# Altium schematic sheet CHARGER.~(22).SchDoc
size A3; SheetNumber: 2; SheetTotal: 14
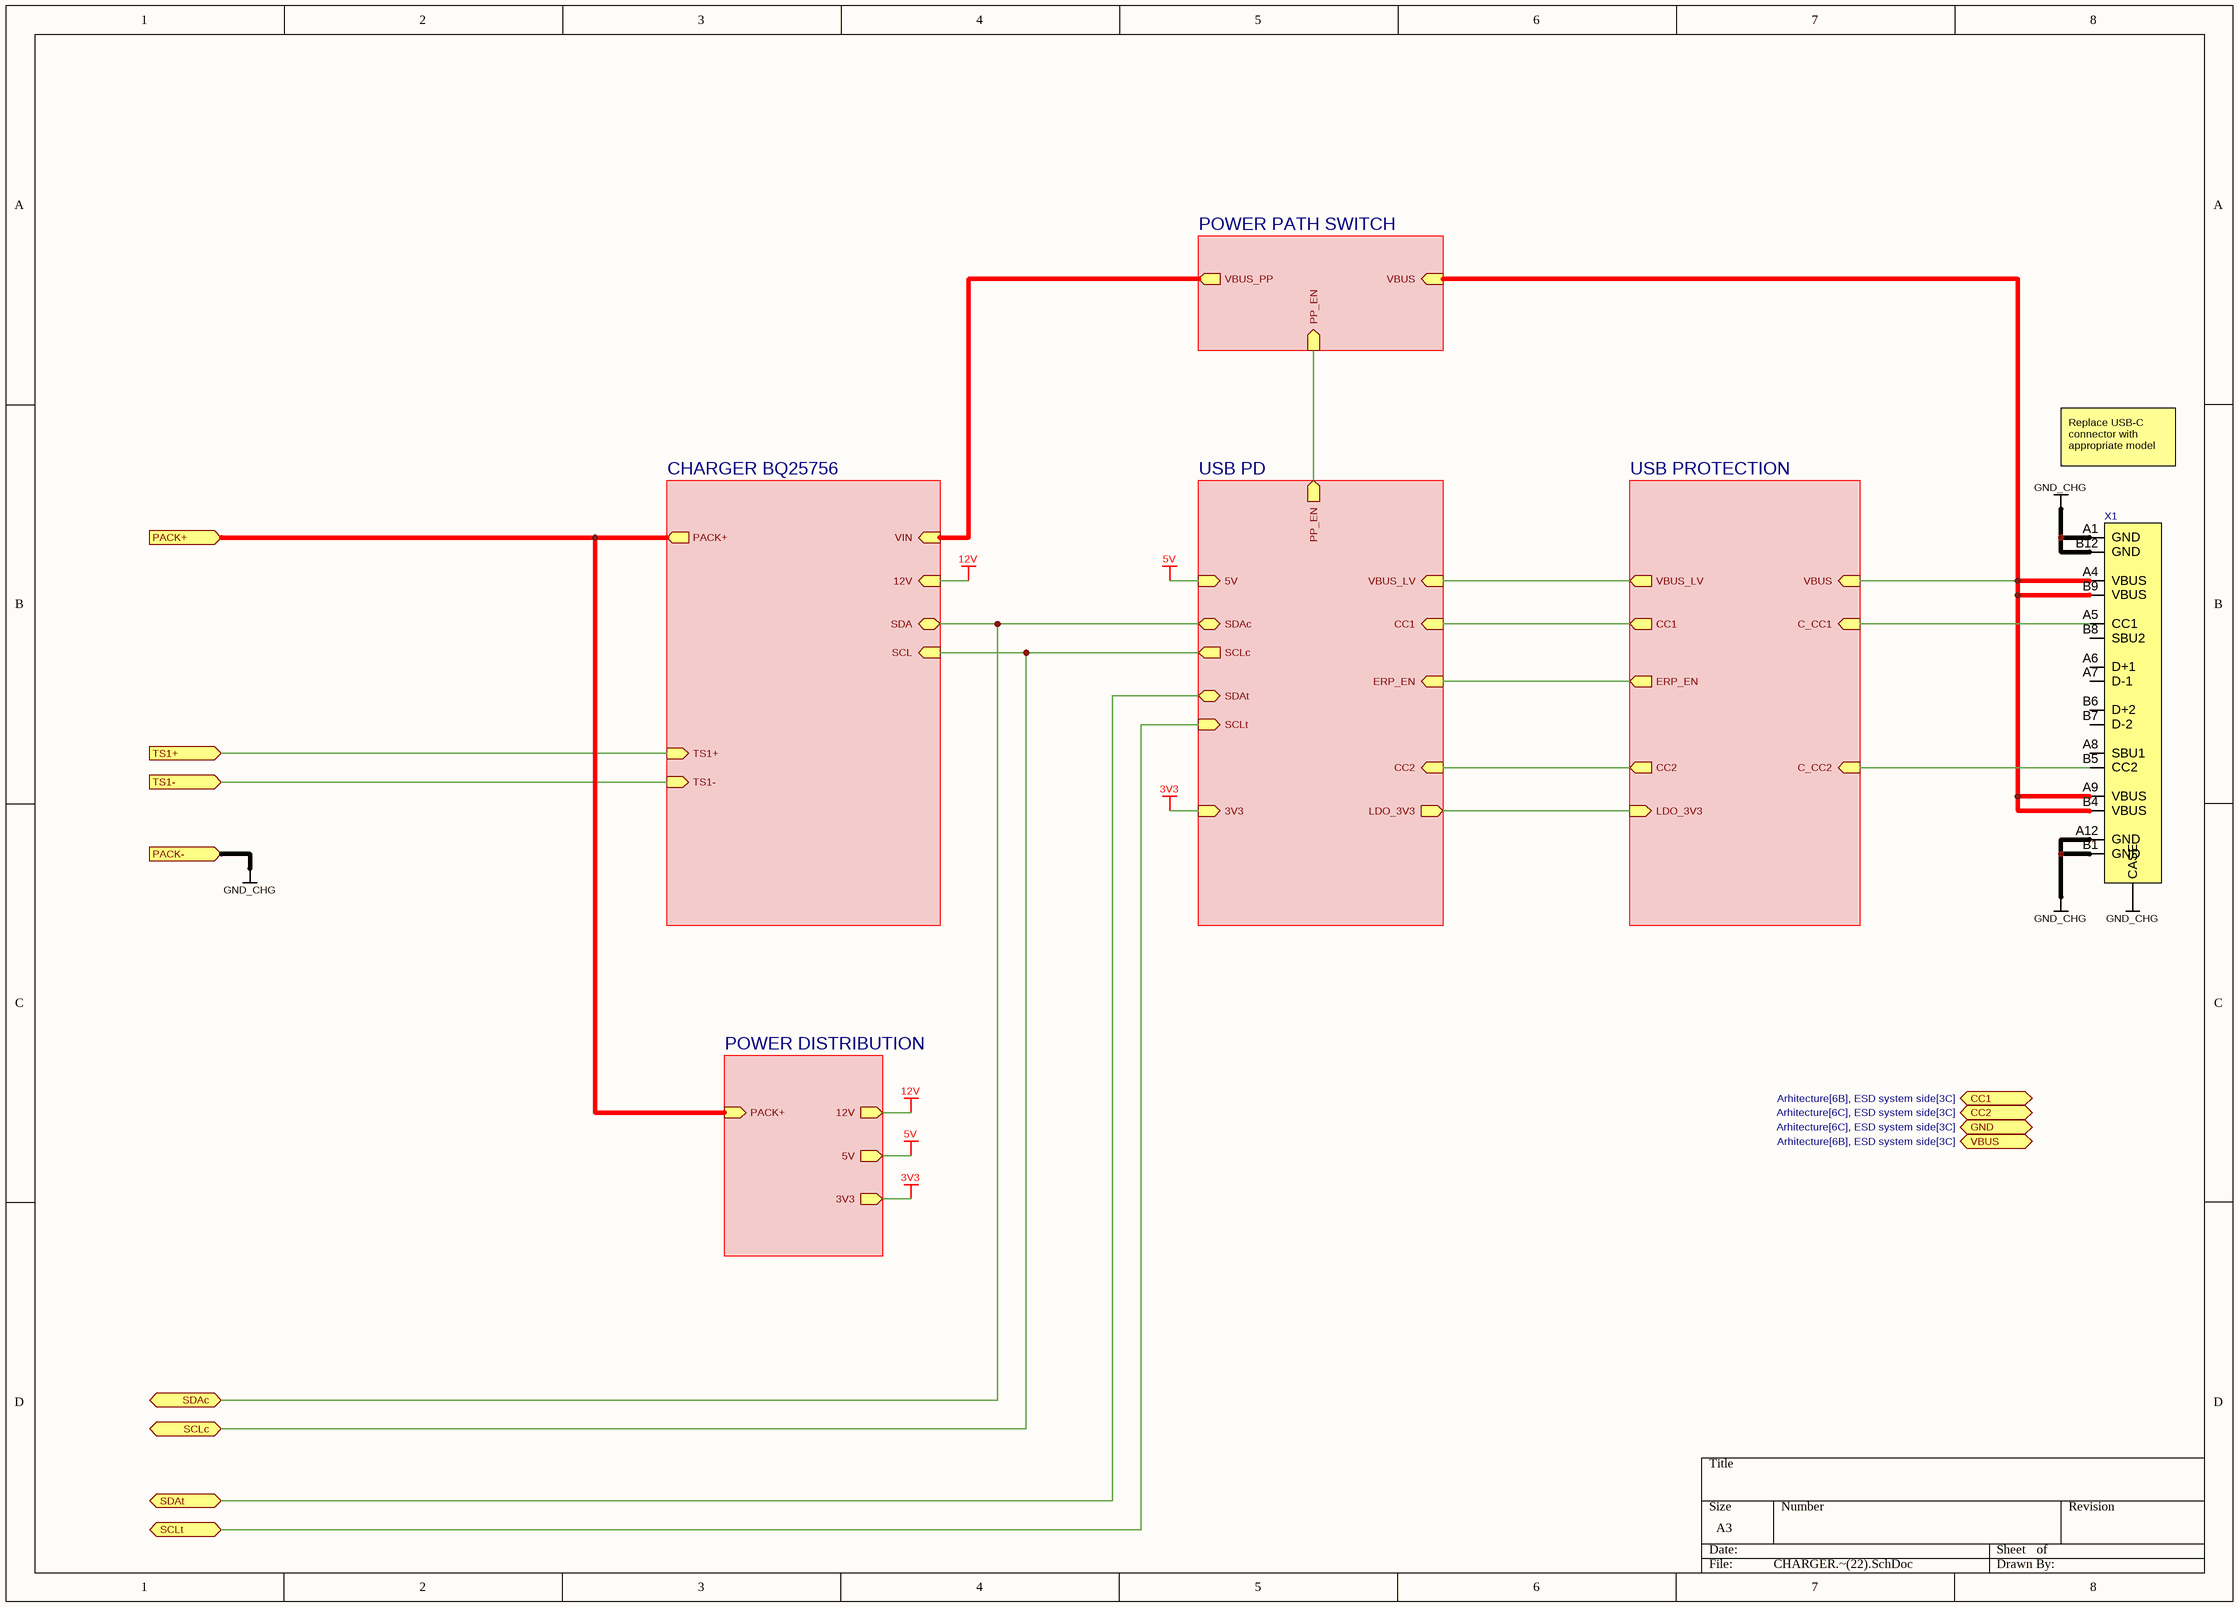
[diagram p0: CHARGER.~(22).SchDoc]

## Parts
X1  TYPE-C 16P LTH6.8  [TYPE-C 16P LTH6.8]  (value not drawn)

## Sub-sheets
CHARGER BQ25756 = Charger BQ25756.SchDoc: PACK+ (out), VIN (in), SDA (bidir), SCL (in), 12V (in), TS1+ (in), TS1- (in)
POWER DISTRIBUTION = Power distribution.SchDoc: PACK+ (in), 12V (out), 5V (out), 3V3 (out)
POWER PATH SWITCH = Power path switch.SchDoc: VBUS (in), VBUS_PP (out), PP_EN (in)
USB PD = USB PD.SchDoc: VBUS_LV (in), ERP_EN (in), CC1 (in), LDO_3V3 (out), SDAc (bidir), SCLc (out), 5V (in), 3V3 (in), CC2 (in), PP_EN (out), SDAt (bidir), SCLt (in)
USB PROTECTION = USB protection.SchDoc: VBUS (in), C_CC1 (in), C_CC2 (in), VBUS_LV (out), ERP_EN (out), CC1 (out), LDO_3V3 (in), CC2 (out)

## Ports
CC1 (bidir, see Arhitecture[6B], ESD system side[3C]), CC2 (bidir, see Arhitecture[6C], ESD system side[3C]), GND (bidir, see Arhitecture[6C], ESD system side[3C]), PACK+ (in, see Arhitecture[6B], BMS[8A], BQ76952 BMS[8A], Charger BQ25756[1A], Power distribution[3A]), PACK- (in, see Arhitecture[6C], BMS[8D], ESD system side[3C]), SCLc (bidir, see Arhitecture[6C], USB PD[7B]), SCLt (bidir, see Arhitecture[6C], USB PD[7B]), SDAc (bidir, see Arhitecture[6C], USB PD[7B]), SDAt (bidir, see Arhitecture[6C], USB PD[7B]), TS1+ (in, see Arhitecture[6B], Charger BQ25756[2C]), TS1- (in, see Arhitecture[6B], Charger BQ25756[2C]), VBUS (bidir, see Arhitecture[6B], ESD system side[3C])

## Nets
3V3: sheet USB PD/3V3, sheet POWER DISTRIBUTION/3V3
5V: sheet USB PD/5V, sheet POWER DISTRIBUTION/5V
12V: sheet CHARGER BQ25756/12V, sheet POWER DISTRIBUTION/12V
GND_CHG: X1.A1(GND) X1.A12(GND) X1.B1(GND) X1.B12(GND) X1.CASE ; port PACK-
PACK+: port PACK+, sheet CHARGER BQ25756/PACK+, sheet POWER DISTRIBUTION/PACK+
SCLc: port SCLc, sheet USB PD/SCLc, sheet CHARGER BQ25756/SCL
SCLt: port SCLt, sheet USB PD/SCLt
SDAc: port SDAc, sheet USB PD/SDAc, sheet CHARGER BQ25756/SDA
SDAt: port SDAt, sheet USB PD/SDAt
TS1+: port TS1+, sheet CHARGER BQ25756/TS1+
TS1-: port TS1-, sheet CHARGER BQ25756/TS1-
NetX1_A4: X1.A4(VBUS) X1.A9(VBUS) X1.B4(VBUS) X1.B9(VBUS) ; sheet USB PROTECTION/VBUS, sheet POWER PATH SWITCH/VBUS
NetX1_A5: X1.A5(CC1) ; sheet USB PROTECTION/C_CC1
NetX1_B5: X1.B5(CC2) ; sheet USB PROTECTION/C_CC2
(unnamed): sheet USB PROTECTION/VBUS_LV, sheet USB PD/VBUS_LV
(unnamed): sheet USB PROTECTION/ERP_EN, sheet USB PD/ERP_EN  [a separate net that carries the same name]
(unnamed): sheet USB PROTECTION/CC1, sheet USB PD/CC1  [a separate net that carries the same name]
(unnamed): sheet USB PROTECTION/LDO_3V3, sheet USB PD/LDO_3V3  [a separate net that carries the same name]
(unnamed): sheet USB PROTECTION/CC2, sheet USB PD/CC2  [a separate net that carries the same name]
(unnamed): sheet USB PD/PP_EN, sheet POWER PATH SWITCH/PP_EN  [a separate net that carries the same name]
(unnamed): sheet POWER PATH SWITCH/VBUS_PP, sheet CHARGER BQ25756/VIN  [a separate net that carries the same name]

Not connected (* = marked no-connect by the designer): X1 A6(D+1) A7(D-1) A8(SBU1) B6(D+2) B7(D-2) B8(SBU2)

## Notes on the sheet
- Replace USB-C connector with appropriate model

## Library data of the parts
X1 = TYPE-C 16P LTH6.8: USB-C 16P SMD Vertical 6.50mmH; Manufacturer: Shou Han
